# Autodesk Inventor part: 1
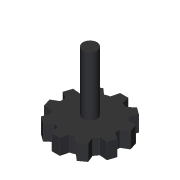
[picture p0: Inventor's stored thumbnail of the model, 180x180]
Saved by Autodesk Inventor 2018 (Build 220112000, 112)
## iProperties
Created: 2017-05
Part Number: 1
Material: Generic
Document SubType Name: Modeling
Designer: CADCIM 00
Density: 1 g/cm^3
Appearance: Default
Author: CADCIM 00
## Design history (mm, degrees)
sketch "Sketch1"
  geometry: L1 (-3.765, 16.614)-(-2.561, 21.495); L2 (-2.561, 21.495)-(2.518, 21.495); L3 (2.518, 21.495)-(3.613, 16.648); L4 (-12.811, 11.228)-(-14.706, 15.884); L5 (-14.706, 15.884)-(-10.598, 18.87); L6 (-10.598, 18.87)-(-6.862, 15.592); L7 (-16.964, 1.554)-(-21.234, 4.206); L8 (-21.234, 4.206)-(-19.665, 9.037); L9 (-19.665, 9.037)-(-14.716, 8.581); L10 (-14.637, -8.714)-(-19.651, -9.078); L11 (-19.651, -9.078)-(-21.221, -4.248); L12 (-21.221, -4.248)-(-16.949, -1.708); L13 (-6.72, -15.654)-(-10.562, -18.895); L14 (-10.562, -18.895)-(-14.671, -15.91); L15 (-14.671, -15.91)-(-12.708, -11.344); L16 (3.765, -16.614)-(2.561, -21.495); L17 (2.561, -21.495)-(-2.518, -21.495); L18 (-2.518, -21.495)-(-3.613, -16.648); L19 (12.811, -11.228)-(14.706, -15.884); L20 (14.706, -15.884)-(10.598, -18.87); L21 (10.598, -18.87)-(6.862, -15.592); L22 (16.964, -1.554)-(21.234, -4.206); L23 (21.234, -4.206)-(19.665, -9.037); L24 (19.665, -9.037)-(14.716, -8.581); L25 (14.637, 8.714)-(19.651, 9.078); L26 (19.651, 9.078)-(21.221, 4.248); L27 (21.221, 4.248)-(16.949, 1.708); L28 (6.72, 15.654)-(10.562, 18.895); L29 (10.562, 18.895)-(14.671, 15.91); L30 (14.671, 15.91)-(12.708, 11.344); A1 r 17.035 centre (0, 0) between (-3.765, 16.614) and (-6.862, 15.592); A2 r 17.035 centre (0, 0) between (-12.811, 11.228) and (-14.716, 8.581); A3 r 17.035 centre (0, 0) between (-16.964, 1.554) and (-16.949, -1.708); A4 r 17.035 centre (0, 0) between (-14.637, -8.714) and (-12.708, -11.344); A5 r 17.035 centre (0, 0) between (-6.72, -15.654) and (-3.613, -16.648); A6 r 17.035 centre (0, 0) between (3.765, -16.614) and (6.862, -15.592); A7 r 17.035 centre (0, 0) between (12.811, -11.228) and (14.716, -8.581); A8 r 17.035 centre (0, 0) between (16.964, -1.554) and (16.949, 1.708); A9 r 17.035 centre (0, 0) between (14.637, 8.714) and (12.708, 11.344); A10 r 17.035 centre (0, 0) between (6.72, 15.654) and (3.613, 16.648); 1 further point
  constraints: 60 end point, 20 point on circle, 10 centre point, 1 coincident, 1 horizontal, 71 other
  dimensions: "d2" = 360 deg dimension on A1.centre L1.start (derived)
extrude "Extrusion1" new body sketch "Sketch1" distance "d4" = 10; taper "d5" = 0 deg
sketch "Sketch2"
  geometry: C1 r 4.406 at (0, 0); 1 further point
  constraints: 1 centre point, 1 coincident
extrude "Extrusion2" join sketch "Sketch2" distance "d6" = 37.5; taper "d7" = 0 deg
body "Solid1"
